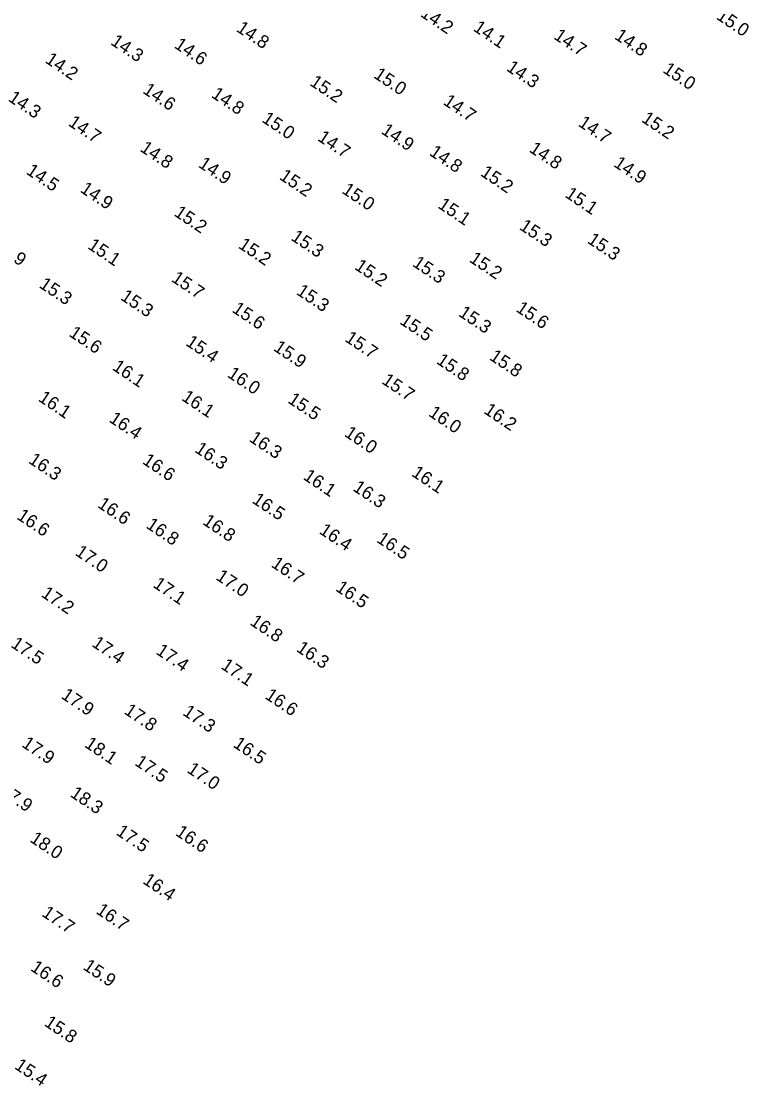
# Model space of a CAD drawing. Extents: x 815352 to 820877, y 582403 to 597439.
# Drawn here: x 817369.3 to 817648.7, y 584825.7 to 585234.6 of the extents above; entities that cross this region are included whole.
import ezdxf

# ---------------------------------------------------------------- set-up
doc = ezdxf.new("R2010")
doc.units = 0
doc.layers.add('V-TOPO-SOUN', color=7, linetype='Continuous')

msp = doc.modelspace()

# ---------------------------------------------------------------- texts
at = {"layer": 'V-TOPO-SOUN'}
for s, p in [('14.2 ', (817522.29, 585236.72)), ('15.0 ', (817635.97, 585235.72)), ('14.8 ', (817451.55, 585231.01)), ('14.1 ', (817542.56, 585231.25)), ('14.7 ', (817573.5, 585228.13)), ('14.8 ', (817596.86, 585228.09)), ('14.3 ', (817403.29, 585225.93)), ('14.6 ', (817427.7, 585224.67)), ('14.2 ', (817378.1, 585218.97)), ('14.3 ', (817555.29, 585215.92)), ('15.0 ', (817615.4, 585215.21)), ('15.0 ', (817504.31, 585213.18)), ('14.6 ', (817415.6, 585207.29)), ('15.2 ', (817479.77, 585210.28)), ('14.3 ', (817363.89, 585204.27)), ('14.8 ', (817441.94, 585205.68)), ('14.7 ', (817531.02, 585202.93)), ('14.7 ', (817386.96, 585194.82)), ('15.0 ', (817461.37, 585196.21)), ('14.7 ', (817582.89, 585194.63)), ('15.2 ', (817607.23, 585196.27)), ('14.9 ', (817507.2, 585191.77)), ('14.7 ', (817482.76, 585189.05)), ('14.8 ', (817414.58, 585184.98)), ('14.8 ', (817525.73, 585183.41)), ('14.8 ', (817564.05, 585184.72)), ('14.9 ', (817436.96, 585178.88)), ('14.9 ', (817596.5, 585179.11)), ('14.5 ', (817370.81, 585176.22)), ('15.2 ', (817468.09, 585174.19)), ('15.2 ', (817545.32, 585175.57)), ('14.9 ', (817391.55, 585169.27)), ('15.0 ', (817492.11, 585168.89)), ('15.1 ', (817577.83, 585167.31)), ('15.1 ', (817528.98, 585163.18)), ('15.2 ', (817427.64, 585160.15)), ('15.3 ', (817560.28, 585154.93)), ('15.3 ', (817472.52, 585150.83)), ('15.3 ', (817586.4, 585149.71)), ('14.9 ', (817358.22, 585147.58)), ('15.1 ', (817394.43, 585147.56)), ('15.2 ', (817452.31, 585147.78)), ('15.2 ', (817541.06, 585142.46)), ('15.2 ', (817496.99, 585139.61)), ('15.3 ', (817519.21, 585140.82)), ('15.7 ', (817426.59, 585134.95)), ('15.3 ', (817375.8, 585132.59)), ('15.3 ', (817474.62, 585129.96)), ('15.3 ', (817407.03, 585127.93)), ('15.6 ', (817449.91, 585123.17)), ('15.3 ', (817536.89, 585121.66)), ('15.6 ', (817558.97, 585123.4)), ('15.5 ', (817514.32, 585118.64)), ('15.6 ', (817387.25, 585113.91)), ('15.4 ', (817432.1, 585110.38)), ('15.7 ', (817493.25, 585111.95)), ('15.9 ', (817465.83, 585108.38)), ('15.8 ', (817548.77, 585104.86)), ('16.1 ', (817403.91, 585100.97)), ('15.8 ', (817528.42, 585103.39)), ('16.0 ', (817448.11, 585098.22)), ('15.7 ', (817507.43, 585095.71)), ('16.1 ', (817375.47, 585089)), ('16.1 ', (817430.52, 585089.29)), ('15.5 ', (817471.31, 585088.33)), ('16.2 ', (817546.63, 585084.29)), ('16.4 ', (817402.64, 585080.98)), ('16.0 ', (817525.38, 585083.26)), ('16.3 ', (817456.48, 585073.5)), ('16.0 ', (817493.06, 585075.48)), ('16.3 ', (817435.58, 585069.37)), ('16.3 ', (817371.7, 585065.17)), ('16.6 ', (817415.46, 585064.93)), ('16.1 ', (817518.87, 585060.22)), ('16.1 ', (817477.24, 585058.91)), ('16.3 ', (817496.31, 585054.57)), ('16.6 ', (817398.21, 585048.17)), ('16.5 ', (817457.62, 585049.88)), ('16.6 ', (817367.2, 585043.67)), ('16.8 ', (817416.88, 585040.23)), ('16.8 ', (817438.6, 585041.64)), ('16.4 ', (817483.38, 585038.1)), ('16.5 ', (817505.46, 585034.79)), ('17.0 ', (817389.62, 585029.78)), ('16.7 ', (817464.94, 585025.3)), ('17.0 ', (817443.68, 585020.39)), ('17.1 ', (817419.53, 585017.47)), ('16.5 ', (817489.68, 585016.09)), ('17.2 ', (817376.56, 585013.82)), ('16.8 ', (817456.77, 585003.03)), ('17.5 ', (817364.94, 584994.46)), ('17.4 ', (817396.04, 584994.73)), ('17.4 ', (817420.68, 584991.81)), ('16.3 ', (817474.59, 584992.86)), ('17.1 ', (817445.64, 584986.17)), ('17.9 ', (817384.26, 584974.78)), ('16.6 ', (817462.54, 584974.71)), ('17.8 ', (817408.44, 584968.84)), ('17.3 ', (817430.95, 584968.35)), ('17.9 ', (817369.11, 584956.18)), ('18.1 ', (817393.25, 584956.06)), ('16.5 ', (817450.34, 584956.08)), ('17.5 ', (817412.55, 584949.09)), ('17.0 ', (817432.6, 584946.31)), ('17.9 ', (817360.64, 584937.87)), ('18.3 ', (817387.71, 584937.02)), ('17.5 ', (817405.36, 584922.35)), ('16.6 ', (817428.16, 584922.15)), ('18.0 ', (817372.23, 584919.67)), ('16.4 ', (817415.6, 584903.68)), ('16.7 ', (817397.65, 584892.14)), ('17.7 ', (817376.82, 584891.12)), ('16.6 ', (817372.49, 584870.18)), ('15.9 ', (817392.66, 584870.65)), ('15.8 ', (817377.74, 584848.99)), ('15.4 ', (817366.32, 584832.49))]:
    msp.add_text(s, height=5, rotation=326, dxfattribs=at).set_placement(p)

doc.saveas('drawing.dxf')
